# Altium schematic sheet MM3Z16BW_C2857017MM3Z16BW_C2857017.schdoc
size 127 x 101 mm
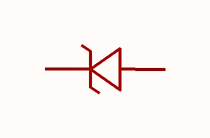
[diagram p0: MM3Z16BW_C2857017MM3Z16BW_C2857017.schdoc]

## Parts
D?  mm3z16bw_c2857017  [SOD-323_L1.8-W1.3-LS2.7-RD]  (value not drawn)

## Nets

Not connected (* = marked no-connect by the designer): D? 1(C) 2(A)

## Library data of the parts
D? = mm3z16bw_c2857017: 二极管配置:1个独立式;稳压值(标称值):16V;稳压值(范围值):15.68V~16.32V;耗散功率(Pd):400mW;; Manufacturer: JSMSEMI(杰盛微); AddInBom: yes; ModelId: e1502c0ed6ee47ccb84fc15c7ca14252; ModelTransform: 106.299,51.181,0,0,0,0,-0.004,-0.005,0; Diode Configuration: 1个独立式; Zener Voltage(Nom): 16V; Reverse Leakage Current (Ir): 100nA@12V; Pd - Power Dissipation: 400mW; Impedance(Zzt): 40Ω; Operating Junction Temperature Range: -55℃~+150℃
